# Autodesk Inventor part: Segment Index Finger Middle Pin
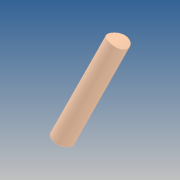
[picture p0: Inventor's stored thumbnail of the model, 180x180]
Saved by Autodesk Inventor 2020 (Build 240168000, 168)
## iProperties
Created: 2019-10
Part Number: Segment Index Finger Middle Pin
Material: GFRP
Document SubType Name: Modeling
Designer: yello
Density: 1.75 g/cm^3
Appearance: Default
Author: yello
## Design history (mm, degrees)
feature "Paliczek WS"
sketch "Sketch1"
  geometry: C1 r 2 at (0, 0); C2 r 35.248 at (0, 0); 1 further point
  constraints: 2 centre point, 1 coincident
  dimensions: "d0" = 4 diameter of C1
extrude "Extrusion1" cut sketch "Sketch1" stored distance "d1" = 100; taper "d2" = 0 deg
loft "Loft1" dims "d3" = 0, "d4" = 90 deg, "d5" = 0, "d6" = 90 deg
  node "Edges1"
  node "Edges2"
body "Solid1"
